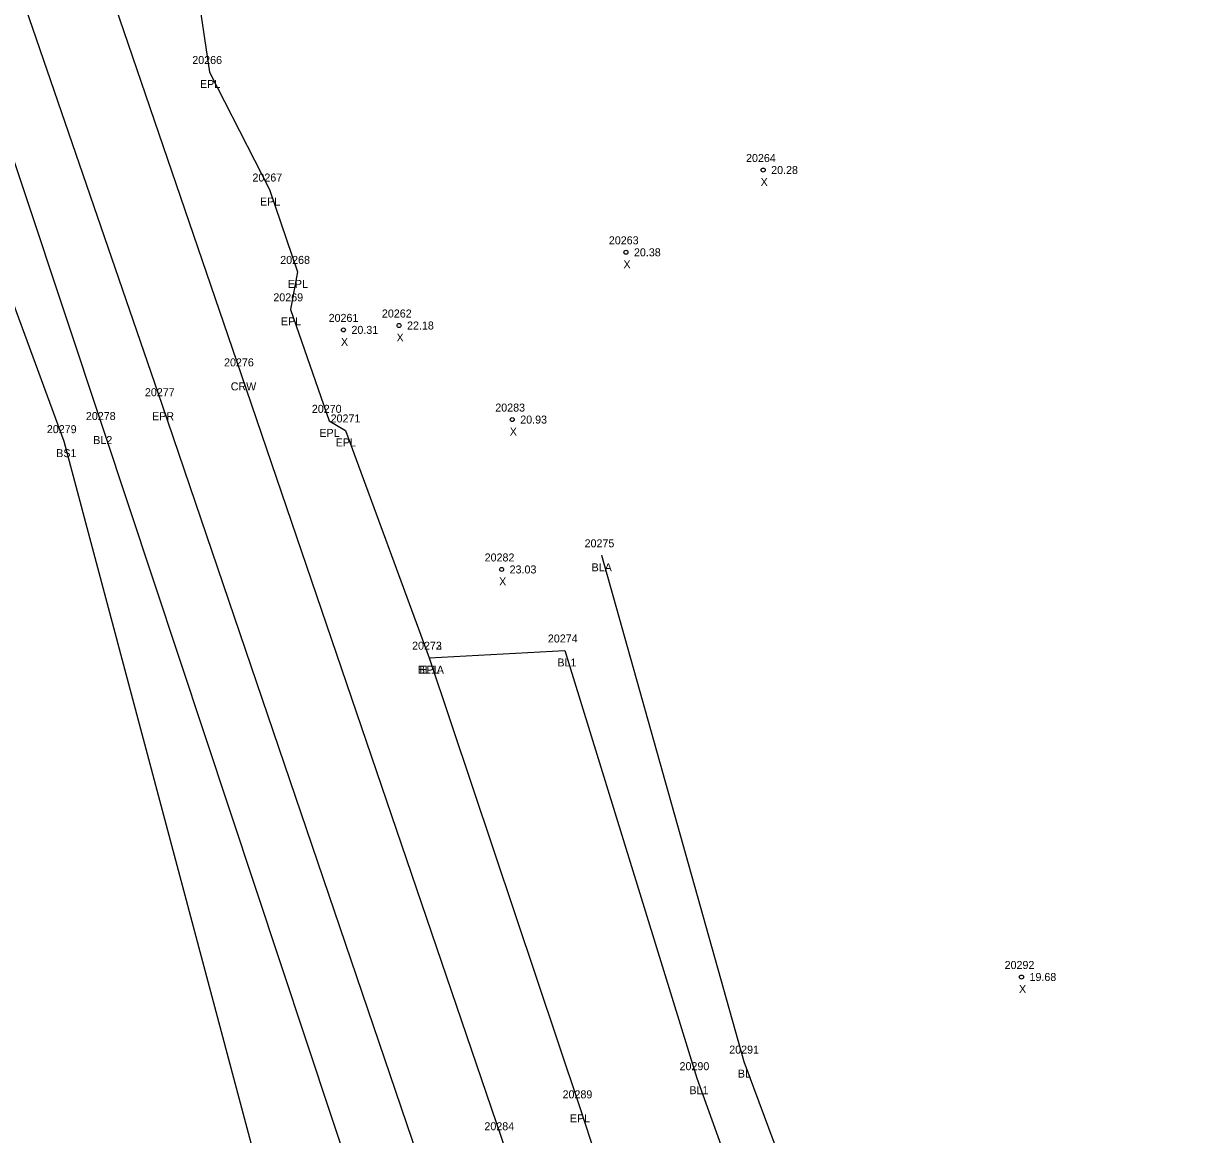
# Model space of a CAD drawing. Extents: x 2432729 to 2433340, y 684958 to 688103.
# Drawn here: x 2433048.8 to 2433196.8, y 686474.5 to 686613.4 of the extents above; entities that cross this region are included whole.
import ezdxf

# ---------------------------------------------------------------- set-up
doc = ezdxf.new("R2010")
doc.units = 0
for name, color, linetype in [('RD_DTM_BkLn1', 7, 'Continuous'), ('RD_DTM_BkLn2', 7, 'Continuous'), ('RD_EX_Road', 7, 'Continuous'), ('RD_EX_Road_txCode', 7, 'Continuous'), ('RD_Sketch8', 7, 'Continuous'), ('RD_SMD_Locator', 7, 'Continuous'), ('RD_SMD_Misc', 7, 'Continuous')]:
    doc.layers.add(name, color=color, linetype=linetype)

msp = doc.modelspace()

# ---------------------------------------------------------------- linework, layer by layer
at = {"layer": 'RD_DTM_BkLn1'}
for points in [[(2432926.02, 687213.66), (2432924.35, 687158.94), (2432925.68, 687108.84), (2432939.7, 687000.92), (2432956.93, 686927.39), (2432975, 686866.8), (2433007.19, 686769.33), (2433041.66, 686669.67), (2433075.97, 686569.51), (2433108.49, 686474.01), (2433123.82, 686426.48), (2433137.99, 686374.7), (2433148.76, 686320.1), (2433154.8, 686269.16), (2433155.78, 686212.93), (2433152.37, 686164.52), (2433145.67, 686113.9), (2433140.38, 686078.83)], [(2432898.98, 687049.37), (2432906.9, 687044.55), (2432919.33, 686997.25), (2432938.84, 686920.72), (2432957.15, 686862.46), (2432990.45, 686763.71), (2433024.84, 686664.51), (2433058.68, 686562.8), (2433090.41, 686467.11), (2433107.21, 686420.87), (2433120.26, 686369.86), (2433132.05, 686313.5), (2433136.59, 686267.4), (2433133.92, 686213.17), (2433133.74, 686165.58), (2433125.69, 686115.89), (2433123.08, 686088.41), (2433128.09, 686081.14)], [(2433121.01, 686546.89), (2433138.81, 686483.59), (2433156.33, 686436.44), (2433172.33, 686382.63), (2433186.16, 686325.49), (2433196.85, 686279.41), (2433196.3, 686212.3), (2433190.98, 686162.16), (2433188.39, 686102.75), (2433180.42, 686073.48), (2433172.96, 686068.93), (2433166.53, 686062.55), (2433152.82, 686065.09)], [(2433099.45, 686534.09), (2433116.42, 686534.99), (2433132.92, 686481.52), (2433149.46, 686435.57), (2433165.09, 686381.24), (2433180.28, 686324.44), (2433185.06, 686269.22), (2433188.28, 686211.65), (2433183.39, 686161.81), (2433176.18, 686106.19), (2433174.91, 686080.31), (2433163.5, 686077.21), (2433155.14, 686078.25)]]:
    msp.add_lwpolyline(points, dxfattribs=at)
at = {"layer": 'RD_DTM_BkLn2'}
msp.add_lwpolyline([(2432916.74, 686973.9), (2432925.37, 686926.35), (2432950.18, 686859.06), (2432982.46, 686761.59), (2433017.67, 686659.38), (2433053.8, 686561.16), (2433080.54, 686460.75), (2433098.39, 686424.64), (2433113.62, 686368.79), (2433123.31, 686312.63), (2433128.29, 686266.56), (2433126.49, 686214.47), (2433123.88, 686164.31), (2433114.46, 686111.82), (2433110.48, 686084.68), (2433120.95, 686072.12)], dxfattribs=at)
at = {"layer": 'RD_EX_Road'}
for points in [[(2432915.64, 687215.4), (2432913.86, 687159.12), (2432915.08, 687107.55), (2432919.97, 687053.4), (2432928.7, 686998.89), (2432946.77, 686924.59), (2432964.57, 686864), (2432997.3, 686766.34), (2433031.44, 686666.38), (2433066.06, 686565.78), (2433098.73, 686469.74), (2433113.88, 686422.91), (2433127.93, 686372.14), (2433139.1, 686314.76), (2433144.47, 686268.02), (2433145.44, 686213), (2433142.32, 686164.92), (2433135.44, 686115.75), (2433128.09, 686081.14)], [(2433070.23, 686619.38), (2433072.02, 686607.31), (2433079.53, 686592.62), (2433082.99, 686582.32), (2433082.14, 686577.64), (2433086.96, 686563.7), (2433088.99, 686562.5), (2433099.45, 686534.09), (2433118.26, 686478), (2433133.83, 686430.29), (2433148.35, 686377.56), (2433159.33, 686322.19), (2433165.5, 686270.06), (2433166.43, 686212.82), (2433163.02, 686162.81), (2433156.19, 686111.14), (2433152.88, 686076.43)]]:
    msp.add_lwpolyline(points, dxfattribs=at)
at = {"layer": 'RD_SMD_Locator'}
for centre, radius in [((2433072.02, 686607.31), 0.001), ((2433141.21, 686595.06), 0.25), ((2433079.53, 686592.62), 0.001), ((2433124.06, 686584.77), 0.25), ((2433082.99, 686582.32), 0.001), ((2433082.14, 686577.64), 0.001), ((2433088.75, 686575.07), 0.25), ((2433095.7, 686575.62), 0.25), ((2433075.97, 686569.51), 0.001), ((2433066.06, 686565.78), 0.001), ((2433058.68, 686562.8), 0.001), ((2433086.96, 686563.7), 0.001), ((2433109.85, 686563.86), 0.25), ((2433088.99, 686562.5), 0.001), ((2433053.8, 686561.16), 0.001), ((2433121.01, 686546.89), 0.001), ((2433108.52, 686545.12), 0.25), ((2433116.42, 686534.99), 0.001), ((2433099.45, 686534.09), 0.001), ((2433099.45, 686534.09), 0.001), ((2433173.5, 686494.17), 0.25), ((2433138.81, 686483.59), 0.001), ((2433132.92, 686481.52), 0.001), ((2433118.26, 686478), 0.001)]:
    msp.add_circle(centre, radius, dxfattribs=at)

# ---------------------------------------------------------------- texts
at = {"layer": 'RD_EX_Road_txCode'}
for s, p in [('20266', (2433069.86, 686608.31)), ('EPL', (2433070.82, 686605.31)), ('20267', (2433077.38, 686593.62)), ('EPL', (2433078.32, 686590.62)), ('20268', (2433080.85, 686583.32)), ('EPL', (2433081.79, 686580.32)), ('20269', (2433079.99, 686578.64)), ('EPL', (2433080.93, 686575.64)), ('20277', (2433063.94, 686566.78)), ('20270', (2433084.8, 686564.7)), ('EPR', (2433064.83, 686563.78)), ('20271', (2433087.15, 686563.5)), ('EPL', (2433085.75, 686561.7)), ('EPL', (2433087.78, 686560.5)), ('20272', (2433097.33, 686535.09)), ('EPL', (2433098.24, 686532.09)), ('20289', (2433116.14, 686479)), ('EPL', (2433117.05, 686476))]:
    msp.add_text(s, height=1, dxfattribs=at).set_placement(p)
at = {"layer": 'RD_Sketch8'}
for s, p in [('20264', (2433139.07, 686596.06)), ('20.28', (2433142.21, 686594.56)), ('X', (2433140.89, 686593.06)), ('20263', (2433121.92, 686585.77)), ('20.38', (2433125.06, 686584.27)), ('X', (2433123.75, 686582.77)), ('20262', (2433093.56, 686576.62)), ('20261', (2433086.9, 686576.07)), ('22.18', (2433096.7, 686575.12)), ('20.31', (2433089.75, 686574.57)), ('X', (2433095.39, 686573.62)), ('X', (2433088.44, 686573.07)), ('20283', (2433107.73, 686564.86)), ('20.93', (2433110.85, 686563.36)), ('X', (2433109.54, 686561.86)), ('20282', (2433106.4, 686546.12)), ('23.03', (2433109.52, 686544.62)), ('X', (2433108.21, 686543.12)), ('20292', (2433171.39, 686495.17)), ('19.68', (2433174.5, 686493.67)), ('X', (2433173.19, 686492.17))]:
    msp.add_text(s, height=1, dxfattribs=at).set_placement(p)
at = {"layer": 'RD_SMD_Misc'}
for s, p in [('20276', (2433073.83, 686570.51)), ('CRW', (2433074.66, 686567.51)), ('20278', (2433056.56, 686563.8)), ('20279', (2433051.68, 686562.16)), ('BL2', (2433057.48, 686560.8)), ('BS1', (2433052.85, 686559.16)), ('20275', (2433118.89, 686547.89)), ('BLA', (2433119.77, 686544.89)), ('20273', (2433097.33, 686535.09)), ('20274', (2433114.3, 686535.99)), ('BL1', (2433115.49, 686532.99)), ('BL1A', (2433098.04, 686532.09)), ('20291', (2433136.97, 686484.59)), ('20290', (2433130.76, 686482.52)), ('BL', (2433138.05, 686481.59)), ('BL1', (2433131.99, 686479.52)), ('20284', (2433106.37, 686475.01))]:
    msp.add_text(s, height=1, dxfattribs=at).set_placement(p)

doc.saveas('drawing.dxf')
